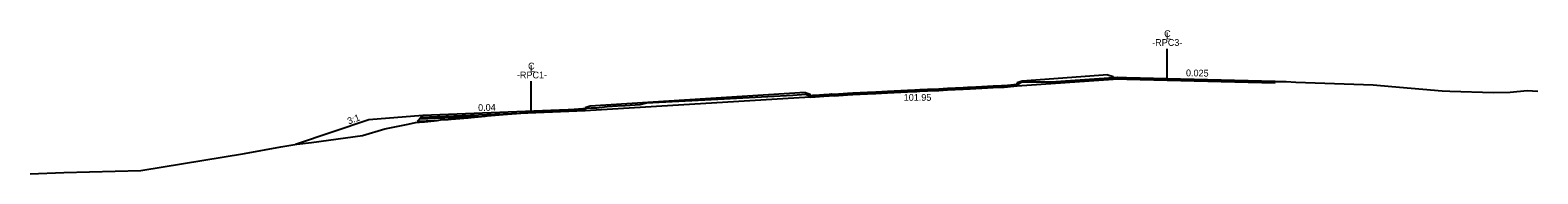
# Model space of a CAD drawing. Extents: x -313 to 385, y -480 to 1023.
# Drawn here: x -313.3 to -90.2, y 519.9 to 541.1 of the extents above; entities that cross this region are included whole.
import ezdxf

# ---------------------------------------------------------------- set-up
doc = ezdxf.new("R2010")
doc.units = 0
for name, color, linetype in [('Exist XS Center Line Elevation Label', 7, 'Continuous'), ('Exist XS Ground Line', 7, 'Continuous'), ('Prop CMT Pvmt Course 3 Wedge', 7, 'Continuous'), ('Prop CMT Pvmt Surface Overlay', 7, 'Continuous'), ('Prop CMT Shld Paved Course 1', 7, 'Continuous'), ('Prop CMT Shld Paved Course 2', 7, 'Continuous'), ('Prop CMT Slope Grass', 7, 'Continuous'), ('Prop Dimension', 7, 'Continuous'), ('Prop XS Label Text', 7, 'Continuous'), ('Prop XS SE Text', 7, 'Continuous'), ('Prop XS Side Slope Text', 7, 'Continuous')]:
    doc.layers.add(name, color=color, linetype=linetype)

msp = doc.modelspace()

# ---------------------------------------------------------------- linework, layer by layer
at = {"layer": 'Exist XS Ground Line'}
msp.add_lwpolyline([(-313.26, 519.9), (-308.29, 520.09), (-296.88, 520.38), (-281.56, 522.9), (-276.17, 523.9), (-273.8, 524.28), (-271.62, 524.55), (-264.12, 525.54), (-260.82, 526.57), (-257.35, 527.26), (-256.24, 527.49), (-255.68, 527.54), (-254.94, 527.6), (-253.48, 527.73), (-253.04, 527.79), (-252.57, 527.87), (-251.44, 527.94), (-250.98, 527.97), (-250.36, 528.03), (-248.47, 528.2), (-248.01, 528.24), (-245.97, 528.42), (-245.65, 528.45), (-243.29, 528.66), (-240.66, 528.85), (-238.45, 529.03), (-235.95, 529.22), (-233.87, 529.38), (-233.44, 529.42), (-231.52, 529.57), (-230.9, 529.61), (-230.27, 529.63), (-229.45, 529.67), (-229.09, 529.71), (-227.93, 529.83), (-226.4, 529.94), (-225.23, 530), (-223.04, 530.15), (-222.41, 530.29), (-222.05, 530.4), (-220.21, 530.5), (-211.55, 530.91), (-200.45, 531.52), (-198.53, 531.65), (-197.87, 531.37), (-197.52, 531.39), (-197.16, 531.41), (-195.84, 531.48), (-195.09, 531.54), (-194.72, 531.59), (-194.35, 531.56), (-192.36, 531.68), (-191.58, 531.72), (-189.4, 531.83), (-188.16, 531.89), (-186.44, 531.98), (-183.48, 532.12), (-182.41, 532.17), (-182.09, 532.2), (-181.67, 532.22), (-180.51, 532.29), (-178.85, 532.35), (-177.54, 532.41), (-175.25, 532.54), (-174.58, 532.58), (-174.2, 532.6), (-171.62, 532.72), (-170.81, 532.78), (-169.58, 532.82), (-169.18, 532.85), (-167.26, 533.05), (-166.56, 533.5), (-162.25, 533.49), (-153.71, 534.07), (-153.07, 534.13), (-152.39, 534.18), (-151.72, 533.94), (-151.31, 533.94), (-149.94, 533.95), (-149.34, 533.94), (-148.41, 533.93), (-146.79, 533.9), (-143.97, 533.85), (-141.68, 533.82), (-139.96, 533.78), (-139.12, 533.77), (-137.85, 533.76), (-136.57, 533.74), (-134.63, 533.7), (-134.02, 533.69), (-131.46, 533.61), (-129.39, 533.57), (-128.91, 533.56), (-127.47, 533.53), (-126.01, 533.45), (-114.58, 533.05), (-111.84, 532.81), (-104.39, 532.16), (-103.23, 532.12), (-96.81, 531.9), (-94.35, 531.97), (-91.8, 532.21), (-90.23, 532.12)], dxfattribs=at)
at = {"layer": 'Prop CMT Pvmt Course 3 Wedge'}
for p in [(-255.67, 527.99), (-253.38, 527.74)]:
    msp.add_line(p, (-256.03, 527.64), dxfattribs=at)
at = {"layer": 'Prop CMT Pvmt Surface Overlay'}
for p, q in [((-129.07, 533.54), (-153.07, 534.14)), ((-129.07, 533.29), (-153.07, 533.89)), ((-231.16, 529.21), (-255.42, 528.24)), ((-231.16, 529.46), (-255.16, 528.5))]:
    msp.add_line(p, q, dxfattribs=at)
for points in [[(-197.87, 531.49), (-197.52, 531.51), (-197.16, 531.53), (-195.84, 531.61), (-195.09, 531.66), (-194.72, 531.72), (-194.35, 531.69), (-192.36, 531.81), (-191.58, 531.85), (-189.4, 531.95), (-188.16, 532.02), (-186.44, 532.1), (-183.48, 532.25), (-182.41, 532.3), (-182.09, 532.32), (-181.67, 532.35), (-180.51, 532.42), (-178.85, 532.48), (-177.54, 532.54), (-175.25, 532.67), (-174.58, 532.71), (-174.2, 532.73), (-171.62, 532.84), (-170.81, 532.9), (-169.58, 532.95), (-169.18, 532.97), (-167.26, 533.17)], [(-197.87, 531.24), (-197.52, 531.26), (-197.16, 531.28), (-195.84, 531.36), (-195.09, 531.41), (-194.72, 531.47), (-194.35, 531.44), (-192.36, 531.56), (-191.58, 531.6), (-189.4, 531.7), (-188.16, 531.77), (-186.44, 531.85), (-183.48, 532), (-182.41, 532.05), (-182.09, 532.07), (-181.67, 532.1), (-180.51, 532.17), (-178.85, 532.23), (-177.54, 532.29), (-175.25, 532.42), (-174.58, 532.46), (-174.2, 532.48), (-171.62, 532.59), (-170.81, 532.65), (-169.58, 532.7), (-169.18, 532.72), (-167.26, 532.92)]]:
    msp.add_lwpolyline(points, dxfattribs=at)
at = {"layer": 'Prop CMT Shld Paved Course 1'}
msp.add_lwpolyline([(-255.16, 528.5), (-255.42, 528.24)], dxfattribs=at)
at = {"layer": 'Prop CMT Shld Paved Course 2'}
msp.add_line((-246.94, 528.33), (-255.68, 527.98), dxfattribs=at)
msp.add_lwpolyline([(-255.42, 528.25), (-255.68, 527.98)], dxfattribs=at)
at = {"layer": 'Prop CMT Slope Grass'}
for p, q in [((-263.16, 527.86), (-274.02, 524.24)), ((-255.16, 528.5), (-263.16, 527.86))]:
    msp.add_line(p, q, dxfattribs=at)
at = {"layer": 'Prop Dimension'}
for p, q in [((-167.26, 532.92), (-153.07, 533.89)), ((-166.51, 533.59), (-167.26, 533.34)), ((-167.26, 532.92), (-167.26, 533.34)), ((-153.82, 534.55), (-166.51, 533.59)), ((-153.82, 534.55), (-153.07, 534.3)), ((-153.07, 533.89), (-153.07, 534.3)), ((-197.87, 531.24), (-231.16, 529.21)), ((-198.62, 531.91), (-230.41, 529.88)), ((-198.62, 531.91), (-197.87, 531.66)), ((-197.87, 531.24), (-197.87, 531.66)), ((-230.41, 529.88), (-231.16, 529.63)), ((-231.16, 529.21), (-231.16, 529.63))]:
    msp.add_line(p, q, dxfattribs=at)
at = {"layer": 'Prop XS Label Text'}
for p, q in [((-145.07, 533.94), (-145.07, 538.38)), ((-239.16, 529.14), (-239.16, 533.59))]:
    msp.add_line(p, q, dxfattribs=at)

# ---------------------------------------------------------------- texts
at = {"layer": 'Exist XS Center Line Elevation Label'}
msp.add_text('101.95', height=1, dxfattribs=at).set_placement((-184.04, 530.69))
at = {"layer": 'Prop XS Label Text'}
for s, p in [('-RPC3-', (-147.28, 538.81)), ('C', (-145.51, 540.12)), ('L', (-145.23, 539.79)), ('C', (-239.61, 535.32)), ('L', (-239.33, 535)), ('-RPC1-', (-241.26, 534.01))]:
    msp.add_text(s, height=1, dxfattribs=at).set_placement(p)
at = {"layer": 'Prop XS SE Text'}
for s, rotation, p in [('0.025', 359.0101, (-142.29, 534.33)), ('0.04', 0.8783, (-246.99, 529.19))]:
    msp.add_text(s, height=1, rotation=rotation, dxfattribs=at).set_placement(p)
at = {"layer": 'Prop XS Side Slope Text'}
msp.add_text('3:1', height=1, rotation=20.6597, dxfattribs=at).set_placement((-266.12, 527.18))

doc.saveas('drawing.dxf')
